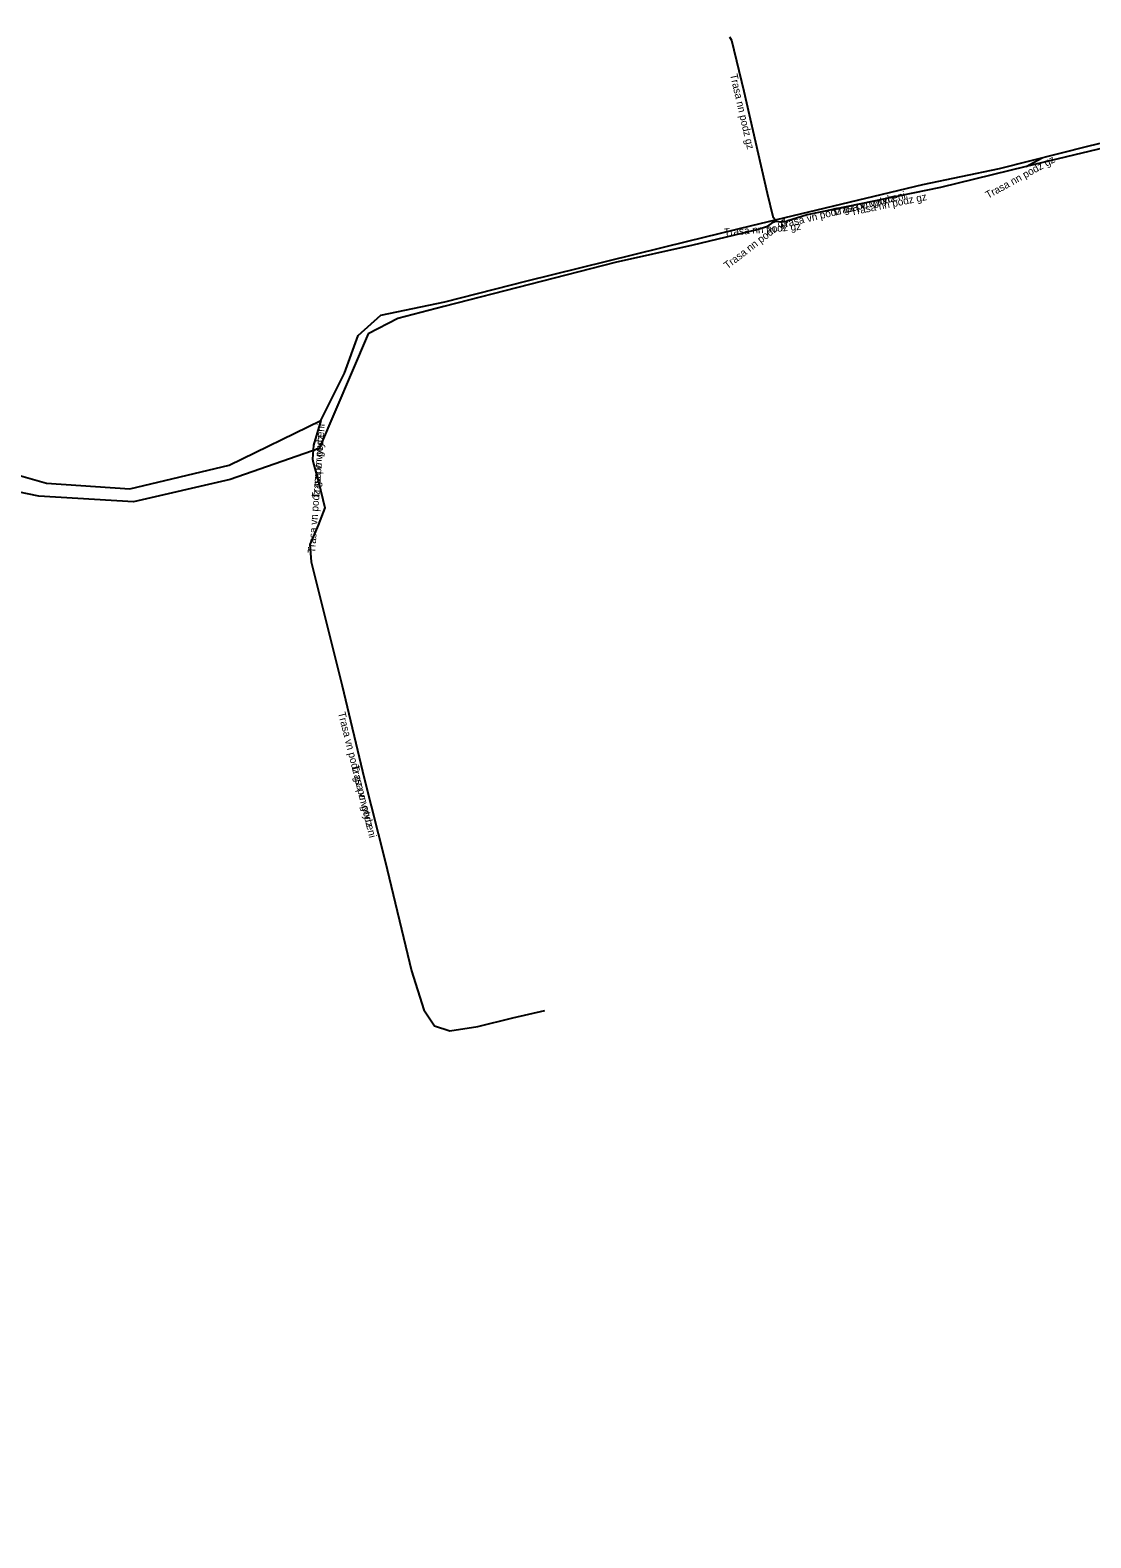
# Model space of a CAD drawing. Extents: x -473162 to -472629, y -1107202 to -1106680.
# Drawn here: x -472793.2 to -472722.3, y -1107175.4 to -1107074.5 of the extents above; entities that cross this region are included whole.
import ezdxf

# ---------------------------------------------------------------- set-up
doc = ezdxf.new("R2010")
doc.units = 0
for name, color, linetype in [('Popiskový text - Ostatní atributy Trasy', 7, 'Continuous'), ('Spojnice NN', 7, 'Continuous'), ('Spojnice VN', 7, 'Continuous')]:
    doc.layers.add(name, color=color, linetype=linetype)

msp = doc.modelspace()

# ---------------------------------------------------------------- linework, layer by layer
at = {"layer": 'Spojnice NN'}
for points in [[(-472746.41, -1107074.99), (-472746.29, -1107075.22), (-472745.46, -1107078.63), (-472743.89, -1107085.46), (-472743.52, -1107087), (-472743.29, -1107087.32)], [(-472690.45, -1107075.38), (-472693.7, -1107075.94), (-472698.29, -1107077.14), (-472702.25, -1107077.71), (-472713.02, -1107080.31), (-472721.28, -1107082.4), (-472726.57, -1107083.67)], [(-472726.57, -1107083.67), (-472732.31, -1107085.06), (-472741.22, -1107086.9), (-472742.58, -1107087.33)], [(-472726.57, -1107083.67), (-472725.5, -1107083.09)], [(-472744.5, -1107087.87), (-472748.86, -1107088.93), (-472754.05, -1107090.09), (-472765.51, -1107093.03), (-472768.58, -1107093.84), (-472770.57, -1107094.86), (-472773.84, -1107102.53), (-472779.8, -1107104.6), (-472786.27, -1107106.09), (-472792.58, -1107105.72), (-472796.6, -1107104.88), (-472804.93, -1107107.02), (-472814.28, -1107109.09), (-472821.76, -1107112.09), (-472823.28, -1107116.48), (-472823.82, -1107121.84), (-472823.15, -1107124.88), (-472821.22, -1107134.78), (-472819.12, -1107143.34), (-472816.44, -1107152.3), (-472814.37, -1107161.26), (-472813.21, -1107170.44), (-472811.95, -1107175.37)], [(-472743.29, -1107087.32), (-472743.63, -1107087.47), (-472743.94, -1107087.71), (-472744.5, -1107087.87)], [(-472743.29, -1107087.32), (-472742.95, -1107087.36), (-472742.58, -1107087.33)]]:
    msp.add_lwpolyline(points, dxfattribs=at)
at = {"layer": 'Spojnice VN'}
for points in [[(-472773.74, -1107100.64), (-472772.16, -1107097.49), (-472771.23, -1107094.96), (-472769.72, -1107093.61), (-472765.45, -1107092.71), (-472759.94, -1107091.32), (-472749.2, -1107088.65), (-472744.92, -1107087.62), (-472733.48, -1107084.87), (-472728.36, -1107083.8), (-472722.36, -1107082.29), (-472718.06, -1107081.25), (-472707.71, -1107078.84), (-472701.11, -1107077.31), (-472697.11, -1107076.27), (-472696.78, -1107075.78), (-472697.09, -1107074.55)], [(-472773.74, -1107100.64), (-472772.16, -1107097.49), (-472771.23, -1107094.96), (-472769.72, -1107093.61), (-472765.45, -1107092.71), (-472759.94, -1107091.32), (-472749.2, -1107088.65), (-472744.92, -1107087.62), (-472733.48, -1107084.87), (-472728.36, -1107083.8), (-472722.36, -1107082.29), (-472718.06, -1107081.25), (-472707.71, -1107078.84), (-472701.11, -1107077.31), (-472697.11, -1107076.27), (-472696.78, -1107075.78), (-472697.09, -1107074.55)], [(-472820.47, -1107110.09), (-472815.74, -1107108.88), (-472809.7, -1107107.26), (-472802.3, -1107105.5), (-472796.66, -1107104.03), (-472794.1, -1107104.27), (-472792.08, -1107104.85), (-472786.5, -1107105.23), (-472779.86, -1107103.64), (-472773.74, -1107100.64)], [(-472820.47, -1107110.09), (-472815.74, -1107108.88), (-472809.7, -1107107.26), (-472802.3, -1107105.5), (-472796.66, -1107104.03), (-472794.1, -1107104.27), (-472792.08, -1107104.85), (-472786.5, -1107105.23), (-472779.86, -1107103.64), (-472773.74, -1107100.64)], [(-472773.74, -1107100.64), (-472774.23, -1107102.29), (-472774.3, -1107103.23), (-472774.24, -1107103.47), (-472773.9, -1107104.72)], [(-472773.74, -1107100.64), (-472774.23, -1107102.29), (-472774.3, -1107103.23), (-472774.24, -1107103.47), (-472773.9, -1107104.72)], [(-472773.9, -1107104.72), (-472773.47, -1107106.49), (-472773.92, -1107107.65), (-472774.47, -1107108.94), (-472774.38, -1107110.11), (-472772.31, -1107118.4), (-472770.83, -1107124.57), (-472769.44, -1107130.12), (-472767.68, -1107137.45), (-472766.86, -1107140.07), (-472766.14, -1107141.12), (-472765.12, -1107141.46), (-472763.25, -1107141.17), (-472760.91, -1107140.59), (-472758.76, -1107140.1)], [(-472773.9, -1107104.72), (-472773.47, -1107106.49), (-472773.92, -1107107.65), (-472774.47, -1107108.94), (-472774.38, -1107110.11), (-472772.31, -1107118.4), (-472770.83, -1107124.57), (-472769.44, -1107130.12), (-472767.68, -1107137.45), (-472766.86, -1107140.07), (-472766.14, -1107141.12), (-472765.12, -1107141.46), (-472763.25, -1107141.17), (-472760.91, -1107140.59), (-472758.76, -1107140.1)]]:
    msp.add_lwpolyline(points, dxfattribs=at)

# ---------------------------------------------------------------- texts
at = {"layer": 'Popiskový text - Ostatní atributy Trasy'}
for s, rotation, p in [('Trasa nn podz gz', 282.9456, (-472746.38, -1107077.52)), ('Trasa nn podz gz', 28.7535, (-472729.13, -1107085.83)), ('Trasa vn podz gz po vytyceni', 13.5223, (-472743.03, -1107087.83)), ('Trasa vn podz', 13.5223, (-472739.44, -1107086.97)), ('Trasa nn podz gz', 11.6681, (-472738.25, -1107086.95)), ('Trasa nn podz gz', 37.7468, (-472746.55, -1107090.55)), ('Trasa nn podz gz', 4.6355, (-472746.76, -1107088.32)), ('Trasa vn podz gz po vytyceni', 85.7412, (-472774.12, -1107109.53)), ('Trasa vn podz', 85.7412, (-472773.84, -1107105.86)), ('Trasa vn podz gz po vytyceni', 284.0605, (-472772.59, -1107120.2)), ('Trasa vn podz', 284.0605, (-472771.7, -1107123.77))]:
    msp.add_text(s, height=0.5, rotation=rotation, dxfattribs=at).set_placement(p)

doc.saveas('drawing.dxf')
